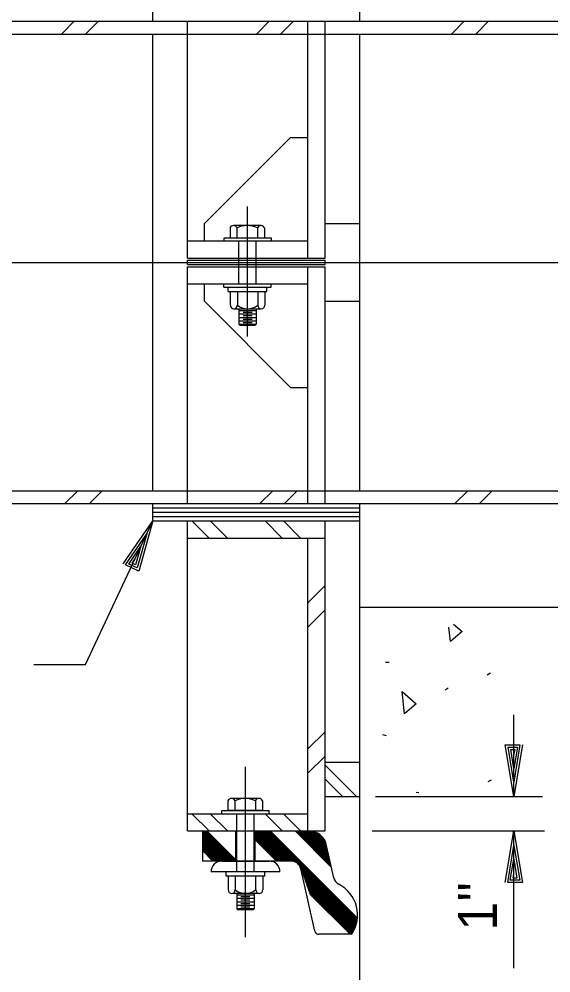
# Model space of a CAD drawing. Extents: x 22369.6 to 22389.4, y 22369.6 to 22386.
# Drawn here: x 22377.302 to 22377.944, y 22377.463 to 22378.617 of the extents above; entities that cross this region are included whole.
import ezdxf

# ---------------------------------------------------------------- set-up
doc = ezdxf.new("R2010")
doc.units = 0
for name, color, linetype in [('Level 1', 7, 'Continuous'), ('Level 2', 7, 'Continuous'), ('Level 4', 7, 'Continuous'), ('Level 44', 7, 'Continuous'), ('Level 50', 7, 'Continuous'), ('Level 7', 7, 'Continuous')]:
    doc.layers.add(name, color=color, linetype=linetype)

msp = doc.modelspace()

# ---------------------------------------------------------------- linework, layer by layer
at = {"layer": 'Level 1'}
for p, q in [((22377.3527, 22378.5983), (22377.3683, 22378.6139)), ((22377.3821, 22378.5983), (22377.3977, 22378.6139)), ((22377.5884, 22378.5983), (22377.604, 22378.6139)), ((22377.6178, 22378.5983), (22377.6335, 22378.6139)), ((22377.8241, 22378.5983), (22377.8397, 22378.6139)), ((22377.8535, 22378.5983), (22377.8692, 22378.6139)), ((22377.5778, 22378.2326), (22377.5778, 22378.3901)), ((22377.5566, 22378.364), (22377.5566, 22378.3522)), ((22377.594, 22378.3668), (22377.5608, 22378.3668)), ((22377.565, 22378.364), (22377.565, 22378.3522)), ((22377.5897, 22378.3641), (22377.5897, 22378.3522)), ((22377.5983, 22378.364), (22377.5983, 22378.3522)), ((22377.5494, 22378.3522), (22377.6067, 22378.3522)), ((22377.5494, 22378.3483), (22377.5494, 22378.3522)), ((22377.5673, 22378.2962), (22377.5673, 22378.3483)), ((22377.5882, 22378.2962), (22377.5882, 22378.3483)), ((22377.6067, 22378.3483), (22377.6067, 22378.3522)), ((22376.6793, 22378.3223), (22379.57, 22378.3223)), ((22377.505, 22378.3249), (22377.6716, 22378.3249)), ((22377.505, 22378.3197), (22377.505, 22378.3249)), ((22377.6716, 22378.3197), (22377.6716, 22378.3249)), ((22377.505, 22378.3197), (22377.6716, 22378.3197)), ((22377.5491, 22378.2923), (22377.5491, 22378.2962)), ((22377.5491, 22378.2923), (22377.6064, 22378.2923)), ((22377.5543, 22378.2871), (22377.5543, 22378.2923)), ((22377.5543, 22378.2871), (22377.6012, 22378.2871)), ((22377.5569, 22378.2871), (22377.5569, 22378.2705)), ((22377.5655, 22378.2871), (22377.5655, 22378.2705)), ((22377.5902, 22378.2871), (22377.5902, 22378.2705)), ((22377.5986, 22378.2871), (22377.5986, 22378.2705)), ((22377.6012, 22378.2871), (22377.6012, 22378.2923)), ((22377.6064, 22378.2923), (22377.6064, 22378.2962)), ((22377.5612, 22378.2663), (22377.5944, 22378.2663)), ((22377.5673, 22378.2663), (22377.5673, 22378.2475)), ((22377.5673, 22378.2642), (22377.5882, 22378.2642)), ((22377.5882, 22378.2663), (22377.5882, 22378.2476)), ((22377.5673, 22378.26), (22377.5882, 22378.26)), ((22377.5673, 22378.2558), (22377.5882, 22378.2558)), ((22377.5726, 22378.2621), (22377.5835, 22378.2621)), ((22377.5726, 22378.2579), (22377.5835, 22378.2579)), ((22377.5726, 22378.2538), (22377.5835, 22378.2538)), ((22377.5673, 22378.2517), (22377.5882, 22378.2517)), ((22377.5673, 22378.2475), (22377.5685, 22378.2465)), ((22377.5673, 22378.2475), (22377.5882, 22378.2475)), ((22377.5685, 22378.2465), (22377.5871, 22378.2465)), ((22377.5726, 22378.2496), (22377.5835, 22378.2496)), ((22377.5882, 22378.2476), (22377.5871, 22378.2465)), ((22377.3571, 22378.0306), (22377.3727, 22378.0462)), ((22377.3866, 22378.0306), (22377.4022, 22378.0462)), ((22377.5928, 22378.0306), (22377.6084, 22378.0462)), ((22377.6223, 22378.0306), (22377.6379, 22378.0462)), ((22377.8285, 22378.0306), (22377.8441, 22378.0462)), ((22377.858, 22378.0306), (22377.8736, 22378.0462)), ((22377.4633, 22378.0254), (22377.7133, 22378.0254)), ((22377.4633, 22378.0202), (22377.7133, 22378.0202)), ((22377.4633, 22378.015), (22377.7133, 22378.015)), ((22377.5314, 22377.9889), (22377.5106, 22378.0098)), ((22377.5535, 22377.9889), (22377.5327, 22378.0098)), ((22377.6198, 22377.9889), (22377.599, 22378.0098)), ((22377.6419, 22377.9889), (22377.6211, 22378.0098)), ((22377.6508, 22377.9107), (22377.6716, 22377.9315)), ((22377.6508, 22377.8812), (22377.6716, 22377.9021)), ((22377.8997, 22377.6764), (22377.8997, 22377.7753)), ((22377.6508, 22377.7339), (22377.6716, 22377.7548)), ((22377.6508, 22377.7045), (22377.6716, 22377.7253)), ((22377.5753, 22377.5064), (22377.5753, 22377.7123)), ((22377.7096, 22377.6764), (22377.6716, 22377.7145)), ((22377.6926, 22377.6764), (22377.6716, 22377.6974)), ((22377.7326, 22377.6764), (22377.9343, 22377.6764)), ((22377.5541, 22377.6713), (22377.5541, 22377.6595)), ((22377.5915, 22377.6741), (22377.5583, 22377.6741)), ((22377.5625, 22377.6713), (22377.5625, 22377.6595)), ((22377.5872, 22377.6714), (22377.5872, 22377.6595)), ((22377.5958, 22377.6713), (22377.5958, 22377.6595)), ((22377.5314, 22377.6348), (22377.5106, 22377.6556)), ((22377.5466, 22377.6595), (22377.6039, 22377.6595)), ((22377.5466, 22377.6556), (22377.5466, 22377.6595)), ((22377.5958, 22377.6595), (22377.5541, 22377.6595)), ((22377.5648, 22377.5853), (22377.5648, 22377.6556)), ((22377.5857, 22377.5853), (22377.5857, 22377.6556)), ((22377.6198, 22377.6348), (22377.599, 22377.6556)), ((22377.6039, 22377.6556), (22377.6039, 22377.6595)), ((22377.6419, 22377.6348), (22377.6211, 22377.6556)), ((22377.5593, 22377.5983), (22377.5232, 22377.6344)), ((22377.5586, 22377.5983), (22377.5232, 22377.6337)), ((22377.5579, 22377.5983), (22377.5232, 22377.633)), ((22377.5572, 22377.5983), (22377.5232, 22377.6323)), ((22377.5565, 22377.5983), (22377.5232, 22377.6316)), ((22377.5558, 22377.5983), (22377.5232, 22377.6309)), ((22377.5551, 22377.5983), (22377.5232, 22377.6302)), ((22377.5544, 22377.5983), (22377.5232, 22377.6295)), ((22377.56, 22377.5983), (22377.5236, 22377.6348)), ((22377.5607, 22377.5983), (22377.5243, 22377.6348)), ((22377.5615, 22377.5983), (22377.525, 22377.6348)), ((22377.5622, 22377.5983), (22377.5257, 22377.6348)), ((22377.5628, 22377.5983), (22377.5264, 22377.6348)), ((22377.5636, 22377.5983), (22377.5271, 22377.6348)), ((22377.5636, 22377.599), (22377.5278, 22377.6348)), ((22377.5636, 22377.5997), (22377.5285, 22377.6348)), ((22377.5636, 22377.5998), (22377.5286, 22377.6348)), ((22377.6233, 22377.5983), (22377.5869, 22377.6348)), ((22377.6226, 22377.5983), (22377.587, 22377.634)), ((22377.6219, 22377.5983), (22377.587, 22377.6333)), ((22377.6212, 22377.5983), (22377.587, 22377.6325)), ((22377.6205, 22377.5983), (22377.587, 22377.6318)), ((22377.6198, 22377.5983), (22377.587, 22377.6311)), ((22377.6191, 22377.5983), (22377.587, 22377.6304)), ((22377.6184, 22377.5983), (22377.587, 22377.6297)), ((22377.624, 22377.5983), (22377.5876, 22377.6348)), ((22377.6248, 22377.5983), (22377.5883, 22377.6348)), ((22377.6255, 22377.5983), (22377.589, 22377.6348)), ((22377.6262, 22377.5983), (22377.5897, 22377.6348)), ((22377.6269, 22377.5983), (22377.5904, 22377.6348)), ((22377.6276, 22377.5983), (22377.5911, 22377.6348)), ((22377.6283, 22377.5983), (22377.5918, 22377.6348)), ((22377.629, 22377.5983), (22377.5925, 22377.6348)), ((22377.6297, 22377.5983), (22377.5932, 22377.6348)), ((22377.6304, 22377.5983), (22377.594, 22377.6348)), ((22377.6311, 22377.5983), (22377.5947, 22377.6348)), ((22377.6318, 22377.5983), (22377.5954, 22377.6348)), ((22377.6325, 22377.5983), (22377.5961, 22377.6348)), ((22377.6336, 22377.598), (22377.5968, 22377.6348)), ((22377.6346, 22377.5977), (22377.5975, 22377.6348)), ((22377.6358, 22377.5972), (22377.5982, 22377.6348)), ((22377.6374, 22377.5963), (22377.5989, 22377.6348)), ((22377.7098, 22377.5246), (22377.5996, 22377.6348)), ((22377.7099, 22377.5252), (22377.6003, 22377.6348)), ((22377.71, 22377.5258), (22377.601, 22377.6348)), ((22377.7101, 22377.5264), (22377.6017, 22377.6348)), ((22377.7102, 22377.527), (22377.6024, 22377.6348)), ((22377.7103, 22377.5276), (22377.6031, 22377.6348)), ((22377.7104, 22377.5282), (22377.6038, 22377.6348)), ((22377.7105, 22377.5289), (22377.6046, 22377.6348)), ((22377.7105, 22377.5295), (22377.6053, 22377.6348)), ((22377.6352, 22377.6348), (22377.6791, 22377.5908)), ((22377.6359, 22377.6348), (22377.6789, 22377.5917)), ((22377.6366, 22377.6348), (22377.6787, 22377.5926)), ((22377.6373, 22377.6348), (22377.6785, 22377.5935)), ((22377.638, 22377.6348), (22377.6783, 22377.5945)), ((22377.6387, 22377.6348), (22377.6781, 22377.5954)), ((22377.6394, 22377.6348), (22377.6779, 22377.5963)), ((22377.6401, 22377.6348), (22377.6777, 22377.5972)), ((22377.6408, 22377.6348), (22377.6775, 22377.5981)), ((22377.6415, 22377.6348), (22377.6773, 22377.599)), ((22377.6422, 22377.6348), (22377.6771, 22377.5999)), ((22377.643, 22377.6348), (22377.6769, 22377.6008)), ((22377.6437, 22377.6348), (22377.6764, 22377.602)), ((22377.6444, 22377.6348), (22377.6765, 22377.6027)), ((22377.6451, 22377.6348), (22377.6763, 22377.6036)), ((22377.6458, 22377.6348), (22377.6761, 22377.6045)), ((22377.6465, 22377.6348), (22377.6759, 22377.6054)), ((22377.6472, 22377.6348), (22377.6757, 22377.6063)), ((22377.6479, 22377.6348), (22377.6755, 22377.6072)), ((22377.6752, 22377.6081), (22377.6486, 22377.6348)), ((22377.675, 22377.609), (22377.6493, 22377.6348)), ((22377.6748, 22377.61), (22377.65, 22377.6348)), ((22377.6746, 22377.6109), (22377.6507, 22377.6348)), ((22377.6744, 22377.6118), (22377.6514, 22377.6348)), ((22377.6742, 22377.6127), (22377.6522, 22377.6347)), ((22377.674, 22377.6136), (22377.6528, 22377.6348)), ((22377.6738, 22377.6145), (22377.6536, 22377.6348)), ((22377.6736, 22377.6154), (22377.6543, 22377.6347)), ((22377.6734, 22377.6163), (22377.6551, 22377.6346)), ((22377.6732, 22377.6172), (22377.656, 22377.6345)), ((22377.673, 22377.6182), (22377.6568, 22377.6343)), ((22377.6728, 22377.6191), (22377.6577, 22377.6341)), ((22377.6725, 22377.62), (22377.6587, 22377.6339)), ((22377.6722, 22377.6211), (22377.6598, 22377.6335)), ((22377.6715, 22377.6227), (22377.6613, 22377.6329)), ((22377.6705, 22377.6246), (22377.6633, 22377.6318)), ((22377.7285, 22377.6348), (22377.9368, 22377.6348)), ((22377.8997, 22377.4689), (22377.8997, 22377.6348)), ((22377.5537, 22377.5983), (22377.5232, 22377.6288)), ((22377.553, 22377.5983), (22377.5232, 22377.6281)), ((22377.5522, 22377.5983), (22377.5232, 22377.6274)), ((22377.5515, 22377.5983), (22377.5232, 22377.6267)), ((22377.5508, 22377.5983), (22377.5232, 22377.626)), ((22377.5501, 22377.5983), (22377.5232, 22377.6253)), ((22377.5494, 22377.5983), (22377.5232, 22377.6245)), ((22377.5487, 22377.5983), (22377.5232, 22377.6238)), ((22377.548, 22377.5983), (22377.5232, 22377.6231)), ((22377.5473, 22377.5983), (22377.5232, 22377.6224)), ((22377.5466, 22377.5983), (22377.5232, 22377.6217)), ((22377.5459, 22377.5983), (22377.5232, 22377.621)), ((22377.5452, 22377.5983), (22377.5232, 22377.6203)), ((22377.5445, 22377.5983), (22377.5232, 22377.6196)), ((22377.5438, 22377.5983), (22377.5232, 22377.6189)), ((22377.5431, 22377.5983), (22377.5232, 22377.6182)), ((22377.6177, 22377.5983), (22377.587, 22377.629)), ((22377.617, 22377.5983), (22377.587, 22377.6283)), ((22377.6163, 22377.5983), (22377.587, 22377.6276)), ((22377.6156, 22377.5983), (22377.587, 22377.6269)), ((22377.6149, 22377.5983), (22377.587, 22377.6262)), ((22377.6141, 22377.5983), (22377.587, 22377.6255)), ((22377.6134, 22377.5983), (22377.587, 22377.6248)), ((22377.6127, 22377.5983), (22377.587, 22377.6241)), ((22377.5423, 22377.5983), (22377.5232, 22377.6175)), ((22377.5416, 22377.5983), (22377.5232, 22377.6168)), ((22377.5409, 22377.5983), (22377.5232, 22377.6161)), ((22377.5402, 22377.5983), (22377.5232, 22377.6154)), ((22377.5395, 22377.5983), (22377.5232, 22377.6147)), ((22377.5388, 22377.5983), (22377.5232, 22377.6139)), ((22377.5381, 22377.5983), (22377.5232, 22377.6132)), ((22377.5374, 22377.5983), (22377.5232, 22377.6125)), ((22377.5367, 22377.5983), (22377.5232, 22377.6118)), ((22377.536, 22377.5983), (22377.5232, 22377.6111)), ((22377.5518, 22377.5801), (22377.5518, 22377.5853)), ((22377.5987, 22377.5801), (22377.5987, 22377.5853)), ((22377.7097, 22377.524), (22377.6404, 22377.5932)), ((22377.7095, 22377.5233), (22377.6416, 22377.5912)), ((22377.7093, 22377.5225), (22377.6421, 22377.5897)), ((22377.7091, 22377.5218), (22377.6426, 22377.5883)), ((22377.7089, 22377.5211), (22377.6431, 22377.5869)), ((22377.7087, 22377.5204), (22377.6436, 22377.5855)), ((22377.7084, 22377.5197), (22377.6441, 22377.584)), ((22377.5987, 22377.5801), (22377.5518, 22377.5801)), ((22377.5544, 22377.5801), (22377.5544, 22377.5635)), ((22377.5628, 22377.5801), (22377.5628, 22377.5635)), ((22377.5875, 22377.5801), (22377.5875, 22377.5635)), ((22377.5961, 22377.5801), (22377.5961, 22377.5635)), ((22377.7082, 22377.519), (22377.6446, 22377.5826)), ((22377.708, 22377.5184), (22377.6451, 22377.5812)), ((22377.7077, 22377.5177), (22377.6456, 22377.5798)), ((22377.7074, 22377.517), (22377.6461, 22377.5784)), ((22377.7071, 22377.5164), (22377.6466, 22377.5769)), ((22377.7069, 22377.5158), (22377.6471, 22377.5755)), ((22377.7066, 22377.5151), (22377.6476, 22377.5741)), ((22377.7063, 22377.5145), (22377.6481, 22377.5727)), ((22377.5544, 22377.5635), (22377.5544, 22377.5635)), ((22377.706, 22377.5139), (22377.6486, 22377.5712)), ((22377.7056, 22377.5133), (22377.6491, 22377.5698)), ((22377.7053, 22377.5127), (22377.6496, 22377.5684)), ((22377.705, 22377.5121), (22377.6501, 22377.567)), ((22377.7046, 22377.5116), (22377.6506, 22377.5655)), ((22377.7043, 22377.511), (22377.6511, 22377.5641)), ((22377.7039, 22377.5104), (22377.6516, 22377.5627)), ((22377.7035, 22377.5099), (22377.6521, 22377.5613)), ((22377.5918, 22377.5593), (22377.5586, 22377.5593)), ((22377.5648, 22377.5593), (22377.5648, 22377.5406)), ((22377.5857, 22377.5572), (22377.5648, 22377.5572)), ((22377.5857, 22377.553), (22377.5648, 22377.553)), ((22377.5857, 22377.5488), (22377.5648, 22377.5488)), ((22377.5805, 22377.5551), (22377.5695, 22377.5551)), ((22377.5805, 22377.5509), (22377.5695, 22377.5509)), ((22377.5857, 22377.5593), (22377.5857, 22377.5405)), ((22377.7027, 22377.5098), (22377.6526, 22377.5598)), ((22377.7018, 22377.5098), (22377.6531, 22377.5584)), ((22377.5857, 22377.5447), (22377.5648, 22377.5447)), ((22377.5648, 22377.5406), (22377.5659, 22377.5395)), ((22377.5857, 22377.5405), (22377.5648, 22377.5405)), ((22377.5846, 22377.5395), (22377.5659, 22377.5395)), ((22377.5805, 22377.5467), (22377.5695, 22377.5467)), ((22377.5805, 22377.5426), (22377.5695, 22377.5426)), ((22377.5857, 22377.5405), (22377.5846, 22377.5395))]:
    msp.add_line(p, q, dxfattribs=at)
for centre, radius, start, end in [((22377.5608, 22378.3622), 0.00456, 22.375, 157.1995), ((22377.5775, 22378.3383), 0.0285, 64.5519, 115.884), ((22377.594, 22378.3621), 0.00469, 23.1675, 155.9991), ((22377.5612, 22378.2705), 0.00422, 180.5659, 359.4341), ((22377.5779, 22378.2866), 0.0203, 232.4343, 307.5657), ((22377.5944, 22378.2705), 0.00421, 180.4975, 359.5025), ((22377.5583, 22377.6695), 0.00456, 22.375, 157.1995), ((22377.575, 22377.6456), 0.0285, 64.5519, 115.884), ((22377.5915, 22377.6694), 0.00469, 23.1675, 155.9991), ((22377.5586, 22377.5635), 0.00421, 180.4975, 359.5025), ((22377.5752, 22377.5796), 0.0203, 232.4343, 307.5657), ((22377.5919, 22377.5635), 0.00422, 180.5659, 359.4341)]:
    msp.add_arc(centre, radius, start, end, dxfattribs=at)
at = {"layer": 'Level 2'}
for p, q in [((22377.7133, 22378.6139), (22377.7133, 22378.9681)), ((22377.4633, 22378.6139), (22377.4633, 22378.6348)), ((22377.0362, 22378.6139), (22378.7654, 22378.6139)), ((22377.505, 22378.3275), (22377.505, 22378.6139)), ((22377.6508, 22378.3275), (22377.6508, 22378.6139)), ((22377.6716, 22378.3275), (22377.6716, 22378.6139)), ((22377.0175, 22378.5983), (22378.7466, 22378.5983)), ((22377.4633, 22378.0462), (22377.4633, 22378.5983)), ((22377.7133, 22378.0462), (22377.7133, 22378.5983)), ((22377.5257, 22378.3692), (22377.6298, 22378.4733)), ((22377.6298, 22378.4733), (22377.6507, 22378.4733)), ((22377.5257, 22378.3483), (22377.5257, 22378.3692)), ((22377.6716, 22378.3692), (22377.7133, 22378.3692)), ((22377.505, 22378.3483), (22377.6508, 22378.3483)), ((22377.505, 22378.3275), (22377.6716, 22378.3275)), ((22377.505, 22378.3171), (22377.6716, 22378.3171)), ((22377.505, 22378.0306), (22377.505, 22378.3171)), ((22377.6508, 22378.0306), (22377.6508, 22378.3171)), ((22377.6716, 22378.0306), (22377.6716, 22378.3171)), ((22377.505, 22378.2962), (22377.6508, 22378.2962)), ((22377.5257, 22378.2754), (22377.5257, 22378.2962)), ((22377.5257, 22378.2754), (22377.6298, 22378.1712)), ((22377.6716, 22378.2754), (22377.7133, 22378.2754)), ((22377.6298, 22378.1712), (22377.6507, 22378.1712)), ((22377.055, 22378.0462), (22378.7841, 22378.0462)), ((22377.0362, 22378.0306), (22378.7654, 22378.0306)), ((22377.4633, 22378.0098), (22377.4633, 22378.0306)), ((22377.7133, 22377.6764), (22377.7133, 22378.0306)), ((22377.4633, 22378.0098), (22377.7133, 22378.0098)), ((22377.4633, 22378.0098), (22377.4633, 22378.0098)), ((22377.505, 22377.6348), (22377.505, 22378.0098)), ((22377.6716, 22377.6348), (22377.6716, 22378.0098)), ((22377.4559, 22377.9941), (22377.4559, 22377.9941)), ((22377.505, 22377.9889), (22377.6716, 22377.9889)), ((22377.6508, 22377.6348), (22377.6508, 22377.9889)), ((22377.6716, 22377.7181), (22377.7133, 22377.7181)), ((22377.8997, 22377.6938), (22377.8997, 22377.6938)), ((22377.6716, 22377.6764), (22377.7133, 22377.6764)), ((22377.8997, 22377.6764), (22377.8997, 22377.6764)), ((22377.505, 22377.6556), (22377.6508, 22377.6556)), ((22377.5535, 22377.6348), (22377.5327, 22377.6556)), ((22377.505, 22377.6348), (22377.6716, 22377.6348)), ((22377.5232, 22377.6348), (22377.5232, 22377.5983)), ((22377.5636, 22377.5983), (22377.5636, 22377.6348)), ((22377.587, 22377.5983), (22377.587, 22377.6348)), ((22377.8997, 22377.6348), (22377.8997, 22377.6348)), ((22377.682, 22377.5781), (22377.6729, 22377.6185)), ((22377.8997, 22377.6174), (22377.8997, 22377.6174)), ((22377.6307, 22377.5983), (22377.5232, 22377.5983)), ((22377.5466, 22377.5983), (22377.6039, 22377.5983)), ((22377.6169, 22377.5853), (22377.5336, 22377.5853)), ((22377.659, 22377.5138), (22377.6421, 22377.5892)), ((22377.7035, 22377.5098), (22377.6641, 22377.5098))]:
    msp.add_line(p, q, dxfattribs=at)
for points in [[(22377.3195, 22377.8361), (22377.382, 22377.8361), (22377.4633, 22378.0098)], [(22377.4275, 22377.9577), (22377.4633, 22378.0098), (22377.4462, 22377.9489), (22377.4302, 22377.9564), (22377.4559, 22377.9941), (22377.4443, 22377.9528), (22377.4341, 22377.9576), (22377.4489, 22377.979), (22377.4424, 22377.9566), (22377.4382, 22377.9586), (22377.4415, 22377.9633)], [(22377.91, 22377.7388), (22377.8997, 22377.6764), (22377.8893, 22377.7388), (22377.907, 22377.7388), (22377.8997, 22377.6938), (22377.8927, 22377.7361), (22377.904, 22377.7361), (22377.8997, 22377.7104), (22377.896, 22377.7334), (22377.9007, 22377.7334), (22377.8997, 22377.7278)], [(22377.8893, 22377.5724), (22377.8997, 22377.6348), (22377.91, 22377.5724), (22377.8923, 22377.5724), (22377.8997, 22377.6174), (22377.9067, 22377.5751), (22377.8953, 22377.5751), (22377.8997, 22377.6008), (22377.9033, 22377.5778), (22377.8987, 22377.5778), (22377.8997, 22377.5834)]]:
    msp.add_lwpolyline(points, dxfattribs=at)
for centre, radius, start, end in [((22377.6526, 22377.6139), 0.0208, 12.6173, 90), ((22377.5466, 22377.5853), 0.013, 90, 180), ((22377.6039, 22377.5853), 0.013, 0, 90), ((22377.6307, 22377.5866), 0.0117, 12.6194, 90), ((22377.6934, 22377.5807), 0.0117, 192.6165, 242.8295), ((22377.669, 22377.5332), 0.0417, 325.7711, 62.8295), ((22377.6641, 22377.515), 0.00521, 192.6179, 270)]:
    msp.add_arc(centre, radius, start, end, dxfattribs=at)
at = {"layer": 'Level 44'}
for p, q in [((22377.7444, 22377.8387), (22377.7489, 22377.8387)), ((22377.8676, 22377.8236), (22377.8714, 22377.8259)), ((22377.8166, 22377.8056), (22377.8204, 22377.8079)), ((22377.7408, 22377.7514), (22377.7453, 22377.7502)), ((22377.8687, 22377.6946), (22377.8725, 22377.6968)), ((22377.7814, 22377.6816), (22377.785, 22377.6813))]:
    msp.add_line(p, q, dxfattribs=at)
msp.add_lwpolyline([(22377.8268, 22377.8849), (22377.8372, 22377.8758), (22377.823, 22377.8639), (22377.8211, 22377.8811)], dxfattribs=at)
msp.add_lwpolyline([(22377.7646, 22377.8033), (22377.7816, 22377.7884), (22377.7675, 22377.7764)], close=True, dxfattribs=at)
at = {"layer": 'Level 50'}
msp.add_line((22377.5986, 22378.2705), (22377.5986, 22378.2705), dxfattribs=at)
at = {"layer": 'Level 7'}
for p, q in [((22377.7133, 22378.6139), (22377.7133, 22380.0223)), ((22377.7133, 22378.0462), (22377.7133, 22378.5983)), ((22377.7133, 22376.3207), (22377.7133, 22378.0306)), ((22377.7133, 22377.9056), (22378.2133, 22377.9056))]:
    msp.add_line(p, q, dxfattribs=at)

# ---------------------------------------------------------------- texts
at = {"layer": 'Level 4'}
msp.add_text("1''", height=0.04688, rotation=90, dxfattribs=at).set_placement((22377.8791, 22377.5144))

doc.saveas('drawing.dxf')
